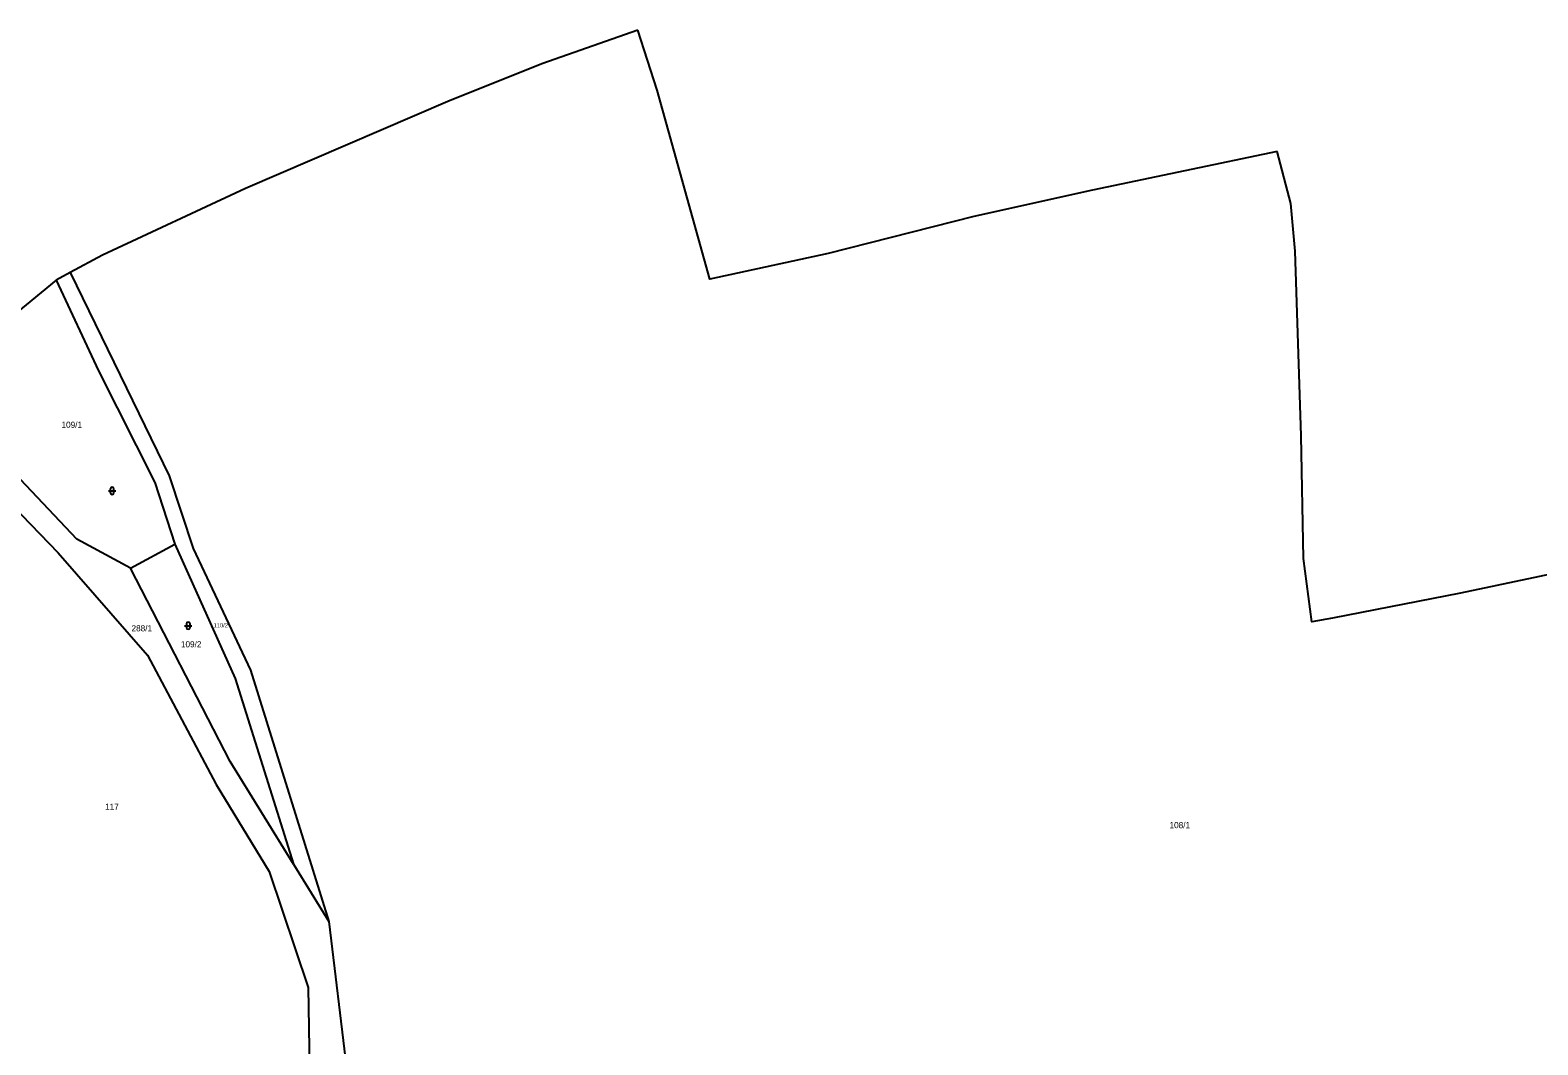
# Model space of a CAD drawing. Extents: x -779723 to -777378, y -1011169 to -1009297.
# Drawn here: x -779077.9 to -778661.4, y -1009880.5 to -1009600.2 of the extents above; entities that cross this region are included whole.
import ezdxf

# ---------------------------------------------------------------- set-up
doc = ezdxf.new("R2010")
doc.units = 0
for name, color, linetype in [('Hranice parcel', 7, 'Continuous'), ('Parcelní čísla', 7, 'Continuous'), ('Značky kultur', 7, 'Continuous')]:
    doc.layers.add(name, color=color, linetype=linetype)

msp = doc.modelspace()

# ---------------------------------------------------------------- linework, layer by layer
at = {"layer": 'Hranice parcel'}
for p, q in [((-778909.99, -1009600.16), (-778936.53, -1009609.5)), ((-778904.63, -1009616.78), (-778909.99, -1009600.16)), ((-779057.84, -1009662.28), (-779066.81, -1009667.14)), ((-779070.64, -1009669.21), (-779104.16, -1009696.65)), ((-779066.81, -1009667.14), (-779070.64, -1009669.21)), ((-779050.17, -1009748.78), (-779037.88, -1009742.18)), ((-779005.09, -1009830.57), (-778995.32, -1009846.4))]:
    msp.add_line(p, q, dxfattribs=at)
for points in [[(-778936.53, -1009609.5), (-778962.51, -1009619.84), (-779018.41, -1009643.9), (-779057.84, -1009662.28)], [(-778733.39, -1009633.72), (-778784.46, -1009644.35), (-778817.24, -1009651.68), (-778857.42, -1009661.85), (-778890.1, -1009668.94), (-778904.63, -1009616.78)], [(-778728.4, -1009661.25), (-778729.66, -1009648.02), (-778733.39, -1009633.72)], [(-778726.11, -1009746.11), (-778726.75, -1009712.18), (-778728.4, -1009661.25)], [(-779070.64, -1009669.21), (-779058.97, -1009694.24), (-779043.46, -1009725.16), (-779037.88, -1009742.18)], [(-779066.81, -1009667.14), (-779047.84, -1009706.06), (-779039.47, -1009723.23), (-779032.85, -1009743.31), (-779016.97, -1009776.97), (-778995.32, -1009846.4)], [(-779050.17, -1009748.78), (-779064.98, -1009740.75), (-779105.59, -1009697.82)], [(-779110.78, -1009702.44), (-779070.14, -1009744.53), (-779045.49, -1009772.81), (-779026.51, -1009808.52), (-779011.87, -1009832.55), (-779001.1, -1009864.61), (-779000.69, -1009886.92)], [(-778599.62, -1009736.93), (-778650.92, -1009748.98), (-778682.79, -1009755.72), (-778718.16, -1009762.55)], [(-779037.88, -1009742.18), (-779021.19, -1009779.25), (-779005.09, -1009830.57)], [(-779005.09, -1009830.57), (-779022.62, -1009802.17), (-779050.17, -1009748.78)], [(-778718.16, -1009762.55), (-778723.83, -1009763.64), (-778726.11, -1009746.11)], [(-778995.32, -1009846.4), (-778990.51, -1009886.89), (-778994.39, -1009886.9)]]:
    msp.add_lwpolyline(points, dxfattribs=at)
at = {"layer": 'Značky kultur'}
for p, q in [((-779056.24, -1009727.42), (-779054.24, -1009727.42)), ((-779055.74, -1009726.92), (-779055.74, -1009727.92)), ((-779054.74, -1009727.92), (-779054.74, -1009726.92)), ((-779035.2, -1009764.67), (-779033.2, -1009764.67)), ((-779034.7, -1009764.17), (-779034.7, -1009765.17)), ((-779033.7, -1009765.17), (-779033.7, -1009764.17))]:
    msp.add_line(p, q, dxfattribs=at)
for centre, start, end in [((-779055.24, -1009726.92), 0, 180), ((-779055.24, -1009727.92), 180, 359.9879), ((-779034.2, -1009764.17), 0, 180), ((-779034.2, -1009765.17), 180, 359.9879)]:
    msp.add_arc(centre, 0.5, start, end, dxfattribs=at)

# ---------------------------------------------------------------- texts
at = {"layer": 'Parcelní čísla'}
for s, height, p in [('109/1', 1.7, (-779069.21, -1009710.02)), ('288/1', 1.7, (-779049.87, -1009766.24)), ('110/2', 1.14, (-779027.18, -1009765.13)), ('109/2', 1.7, (-779036.23, -1009770.65)), ('117', 1.7, (-779057.16, -1009815.52)), ('108/1', 1.7, (-778763.15, -1009820.61))]:
    msp.add_text(s, height=height, dxfattribs=at).set_placement(p)

doc.saveas('drawing.dxf')
